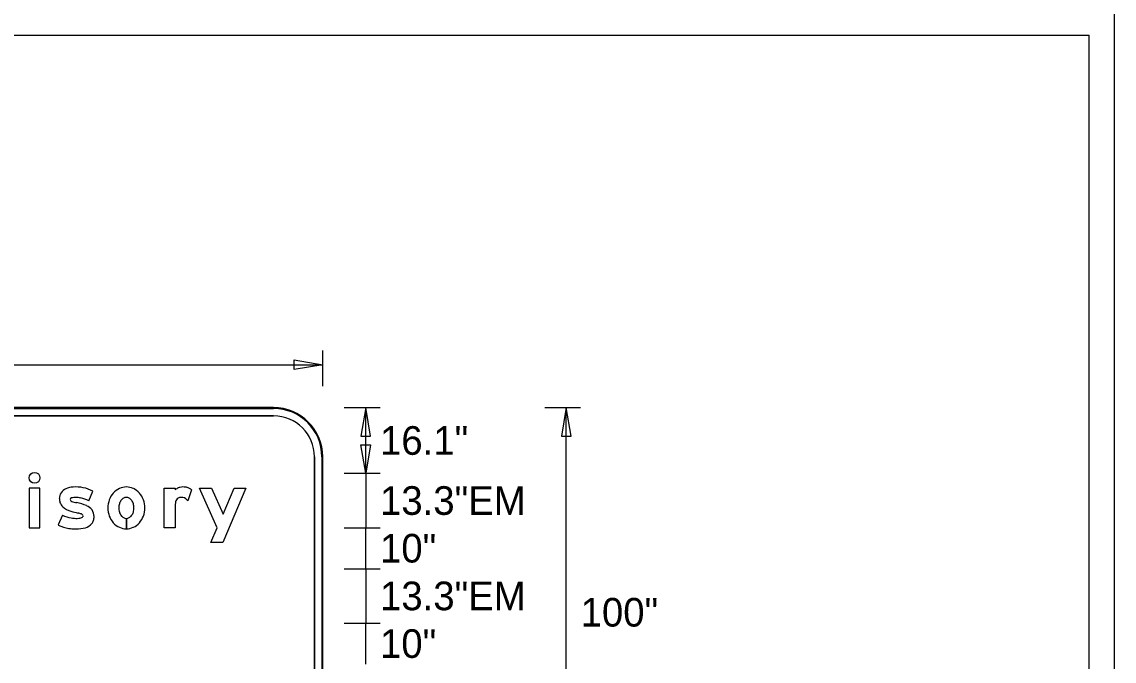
# Model space of a CAD drawing. Extents: x 17890484 to 17890754, y 17897495 to 17897992.
# Drawn here: x 17890542.41 to 17890564.64, y 17897537.69 to 17897550.71 of the extents above; entities that cross this region are included whole.
import ezdxf

# ---------------------------------------------------------------- set-up
doc = ezdxf.new("R2010")
doc.units = 0
for name, color, linetype in [('GSBWFill', 7, 'Continuous'), ('GSColorFill', 7, 'Continuous'), ('GSDims', 7, 'Continuous'), ('GSOutline', 7, 'Continuous'), ('SheetLinesMisc2_dp', 7, 'Continuous')]:
    doc.layers.add(name, color=color, linetype=linetype)

msp = doc.modelspace()

# ---------------------------------------------------------------- linework, layer by layer
at = {"layer": 'GSBWFill'}
for p, q in [((17890547.531, 17897542.854), (17890529.531, 17897542.854)), ((17890529.531, 17897542.687), (17890547.531, 17897542.687)), ((17890548.365, 17897541.854), (17890548.365, 17897533.854)), ((17890548.531, 17897533.854), (17890548.531, 17897541.854)), ((17890543.769, 17897540.955), (17890543.855, 17897541.153)), ((17890545.861, 17897541.181), (17890545.786, 17897540.956)), ((17890543.233, 17897540.663), (17890543.147, 17897540.465)), ((17890544.535, 17897540.386), (17890544.535, 17897540.599)), ((17890544.535, 17897540.599), (17890544.535, 17897540.386)), ((17890543.147, 17897540.465), (17890543.147, 17897540.465))]:
    msp.add_line(p, q, dxfattribs=at)
for points in [[(17890542.555, 17897540.408), (17890542.777, 17897540.408), (17890542.777, 17897541.217), (17890542.555, 17897541.217)], [(17890546.269, 17897541.217), (17890546.503, 17897540.688), (17890546.728, 17897541.217), (17890546.969, 17897541.217), (17890546.498, 17897540.109), (17890546.257, 17897540.109), (17890546.385, 17897540.408), (17890546.027, 17897541.217)]]:
    msp.add_lwpolyline(points, close=True, dxfattribs=at)
msp.add_lwpolyline([(17890545.529, 17897540.856), (17890545.529, 17897540.408), (17890545.307, 17897540.408), (17890545.307, 17897541.217), (17890545.529, 17897541.217), (17890545.529, 17897541.181)], dxfattribs=at)
for radius in [1, 0.833]:
    msp.add_arc((17890547.531, 17897541.854), radius, 0, 90, dxfattribs=at)
msp.add_ellipse((17890542.666, 17897541.425), major_axis=(0, 0.111), ratio=0.999977, dxfattribs=at)
for centre, major_axis, ratio, start_param, end_param in [((17890543.387, 17897541.002), (0, 0.217), 0.999993, 0.398006, 1.570796), ((17890543.482, 17897540.776), (0, 0.462), 0.999993, 0.071378, 0.398007), ((17890543.51, 17897540.642), (0, 0.385), 0.999993, 0, 0.239757), ((17890543.502, 17897540.48), (0, 0.76), 0.999993, 5.800291, 6.352301), ((17890543.51, 17897540.662), (0, 0.364), 0.999993, 6.027142, 6.283185), ((17890544.589, 17897540.832), (0, 0.427), 0.999998, 0.847388, 1.220117), ((17890544.556, 17897540.861), (0, 0.384), 0.999998, 0.438571, 0.847388), ((17890544.535, 17897540.905), (0, 0.334), 0.999998, 0, 0.438571), ((17890544.535, 17897540.912), (0, 0.114), 0.999998, 0, 0.517724), ((17890544.535, 17897540.905), (0, 0.334), 0.999998, 5.844614, 6.283185), ((17890544.535, 17897540.912), (0, 0.114), 0.999998, 5.765461, 6.283185), ((17890544.514, 17897540.861), (0, 0.384), 0.999998, 5.435798, 5.844614), ((17890544.481, 17897540.832), (0, 0.427), 0.999998, 5.063069, 5.435798), ((17890545.752, 17897540.886), (0, 0.37), 0.999991, 0.443663, 0.646229), ((17890545.664, 17897541.07), (0, 0.166), 0.999991, 0.24142, 0.443663), ((17890545.649, 17897540.909), (0, 0.118), 0.999991, 0.067293, 0.293855), ((17890545.693, 17897540.954), (0, 0.285), 0.999991, 6.103268, 6.524606), ((17890545.653, 17897540.85), (0, 0.177), 0.999991, 6.094384, 6.350479), ((17890545.699, 17897540.99), (0, 0.249), 0.999991, 5.846069, 6.103268), ((17890545.674, 17897540.935), (0, 0.31), 0.999991, 5.631644, 5.846069), ((17890543.43, 17897541.002), (0, 0.259), 0.999993, 1.570796, 1.879779), ((17890543.367, 17897540.983), (0, 0.194), 0.999993, 1.879779, 2.42566), ((17890543.523, 17897541.162), (0, 0.432), 0.999993, 2.42566, 2.869403), ((17890543.426, 17897540.983), (0, 0.0332), 0.999993, 0.21891, 1.570796), ((17890543.432, 17897540.983), (0, 0.0388), 0.999993, 1.570796, 2.88808), ((17890543.67, 17897541.735), (0, 0.828), 0.999993, 2.83708, 2.965597), ((17890543.236, 17897539.641), (0, 1.312), 0.999993, 5.901211, 6.060377), ((17890543.485, 17897540.422), (0, 0.604), 0.999993, 5.793797, 6.086746), ((17890543.64, 17897540.635), (0, 0.238), 0.999993, 4.712389, 5.919951), ((17890544.641, 17897540.813), (0, 0.482), 0.999998, 1.220117, 1.570796), ((17890544.641, 17897540.813), (0, 0.482), 0.999998, 1.570796, 1.921476), ((17890544.673, 17897540.813), (0, 0.292), 0.999998, 1.278197, 1.570796), ((17890544.673, 17897540.813), (0, 0.292), 0.999998, 1.570796, 1.863396), ((17890544.605, 17897540.833), (0, 0.222), 0.999998, 0.942, 1.278197), ((17890544.562, 17897540.864), (0, 0.169), 0.999998, 0.517724, 0.942), ((17890544.508, 17897540.864), (0, 0.169), 0.999998, 5.341185, 5.765461), ((17890544.466, 17897540.833), (0, 0.222), 0.999998, 5.004989, 5.341185), ((17890544.398, 17897540.813), (0, 0.292), 0.999998, 4.712389, 5.004989), ((17890544.398, 17897540.813), (0, 0.292), 0.999998, 4.419789, 4.712389), ((17890544.43, 17897540.813), (0, 0.482), 0.999998, 4.712389, 5.063069), ((17890544.43, 17897540.813), (0, 0.482), 0.999998, 4.361709, 4.712389), ((17890545.999, 17897540.855), (0, 0.47), 0.999991, 1.445958, 1.569673), ((17890545.704, 17897540.893), (0, 0.173), 0.999991, 1.188904, 1.450084), ((17890545.647, 17897540.916), (0, 0.111), 0.999991, 0.293855, 1.188904), ((17890545.657, 17897540.874), (0, 0.152), 0.999991, 5.27661, 6.094384), ((17890543.511, 17897541.259), (0, 0.658), 0.999993, 2.70455, 2.991718), ((17890544.148, 17897543.308), (0, 2.667), 0.999993, 2.860128, 2.916667), ((17890543.506, 17897541.104), (0, 0.504), 0.999993, 2.95481, 3.141593), ((17890543.506, 17897541.232), (0, 0.633), 0.999993, 3.141593, 3.238422), ((17890543.276, 17897539.544), (0, 1.197), 0.999993, 5.990951, 6.04928), ((17890543.563, 17897540.752), (0, 0.15), 0.999993, 3.169414, 3.711965), ((17890543.602, 17897540.637), (0, 0.0564), 0.999993, 5.20773, 5.944931), ((17890543.629, 17897540.647), (0, 0.0256), 0.999993, 3.769232, 4.712389), ((17890543.615, 17897540.647), (0, 0.0402), 0.999993, 4.712389, 5.146352), ((17890543.6, 17897540.635), (0, 0.278), 0.999993, 4.42655, 4.712389), ((17890544.589, 17897540.794), (0, 0.427), 0.999998, 1.921476, 2.294205), ((17890544.605, 17897540.792), (0, 0.222), 0.999998, 1.863396, 2.199593), ((17890544.562, 17897540.761), (0, 0.169), 0.999998, 2.199593, 2.623869), ((17890544.535, 17897540.714), (0, 0.114), 0.999998, 2.623869, 3.141593), ((17890544.535, 17897540.714), (0, 0.114), 0.999998, 3.142077, 3.659317), ((17890544.508, 17897540.761), (0, 0.169), 0.999998, 3.659317, 4.083593), ((17890544.466, 17897540.792), (0, 0.222), 0.999998, 4.083593, 4.419789), ((17890544.481, 17897540.794), (0, 0.427), 0.999998, 3.98898, 4.361709), ((17890543.463, 17897541.072), (0, 0.685), 0.999993, 2.661561, 2.999689), ((17890543.444, 17897540.943), (0, 0.554), 0.999993, 2.999689, 3.056979), ((17890543.514, 17897541.747), (0, 1.361), 0.999993, 3.056204, 3.141593), ((17890543.514, 17897541.14), (0, 0.754), 0.999993, 3.141593, 3.39368), ((17890543.63, 17897540.665), (0, 0.265), 0.999993, 3.41426, 4.020407), ((17890543.707, 17897540.603), (0, 0.166), 0.999993, 4.009587, 4.42655), ((17890544.556, 17897540.765), (0, 0.384), 0.999998, 2.294205, 2.703022), ((17890544.535, 17897540.72), (0, 0.334), 0.999998, 2.703022, 3.141593), ((17890544.535, 17897540.72), (0, 0.334), 0.999998, 3.141759, 3.580164), ((17890544.514, 17897540.765), (0, 0.384), 0.999998, 3.580164, 3.98898)]:
    msp.add_ellipse(centre, major_axis=major_axis, ratio=ratio, start_param=start_param, end_param=end_param, dxfattribs=at)
at = {"layer": 'GSColorFill'}
for p, q in [((17890547.531, 17897542.854), (17890529.531, 17897542.854)), ((17890547.531, 17897542.854), (17890529.531, 17897542.854)), ((17890547.531, 17897542.854), (17890529.531, 17897542.854)), ((17890529.531, 17897542.837), (17890547.531, 17897542.837)), ((17890529.531, 17897542.687), (17890547.531, 17897542.687)), ((17890548.365, 17897541.854), (17890548.365, 17897533.854)), ((17890548.515, 17897541.854), (17890548.515, 17897533.854)), ((17890548.531, 17897533.854), (17890548.531, 17897541.854)), ((17890548.531, 17897533.854), (17890548.531, 17897541.854)), ((17890548.531, 17897533.854), (17890548.531, 17897541.854)), ((17890543.769, 17897540.955), (17890543.855, 17897541.153)), ((17890545.861, 17897541.181), (17890545.786, 17897540.956)), ((17890543.233, 17897540.663), (17890543.147, 17897540.465)), ((17890544.535, 17897540.386), (17890544.535, 17897540.599)), ((17890544.535, 17897540.599), (17890544.535, 17897540.386)), ((17890543.147, 17897540.465), (17890543.147, 17897540.465))]:
    msp.add_line(p, q, dxfattribs=at)
for points in [[(17890542.555, 17897540.408), (17890542.777, 17897540.408), (17890542.777, 17897541.217), (17890542.555, 17897541.217)], [(17890546.269, 17897541.217), (17890546.503, 17897540.688), (17890546.728, 17897541.217), (17890546.969, 17897541.217), (17890546.498, 17897540.109), (17890546.257, 17897540.109), (17890546.385, 17897540.408), (17890546.027, 17897541.217)]]:
    msp.add_lwpolyline(points, close=True, dxfattribs=at)
msp.add_lwpolyline([(17890545.529, 17897540.856), (17890545.529, 17897540.408), (17890545.307, 17897540.408), (17890545.307, 17897541.217), (17890545.529, 17897541.217), (17890545.529, 17897541.181)], dxfattribs=at)
for radius in [1, 1, 1, 0.983, 0.833]:
    msp.add_arc((17890547.531, 17897541.854), radius, 0, 90, dxfattribs=at)
msp.add_ellipse((17890542.666, 17897541.425), major_axis=(0, 0.111), ratio=0.999977, dxfattribs=at)
for centre, major_axis, ratio, start_param, end_param in [((17890543.387, 17897541.002), (0, 0.217), 0.999993, 0.398006, 1.570796), ((17890543.482, 17897540.776), (0, 0.462), 0.999993, 0.071378, 0.398007), ((17890543.51, 17897540.642), (0, 0.385), 0.999993, 0, 0.239757), ((17890543.502, 17897540.48), (0, 0.76), 0.999993, 5.800291, 6.352301), ((17890543.51, 17897540.662), (0, 0.364), 0.999993, 6.027142, 6.283185), ((17890544.589, 17897540.832), (0, 0.427), 0.999998, 0.847388, 1.220117), ((17890544.556, 17897540.861), (0, 0.384), 0.999998, 0.438571, 0.847388), ((17890544.535, 17897540.905), (0, 0.334), 0.999998, 0, 0.438571), ((17890544.535, 17897540.912), (0, 0.114), 0.999998, 0, 0.517724), ((17890544.535, 17897540.905), (0, 0.334), 0.999998, 5.844614, 6.283185), ((17890544.535, 17897540.912), (0, 0.114), 0.999998, 5.765461, 6.283185), ((17890544.514, 17897540.861), (0, 0.384), 0.999998, 5.435798, 5.844614), ((17890544.481, 17897540.832), (0, 0.427), 0.999998, 5.063069, 5.435798), ((17890545.752, 17897540.886), (0, 0.37), 0.999991, 0.443663, 0.646229), ((17890545.664, 17897541.07), (0, 0.166), 0.999991, 0.24142, 0.443663), ((17890545.649, 17897540.909), (0, 0.118), 0.999991, 0.067293, 0.293855), ((17890545.693, 17897540.954), (0, 0.285), 0.999991, 6.103268, 6.524606), ((17890545.653, 17897540.85), (0, 0.177), 0.999991, 6.094384, 6.350479), ((17890545.699, 17897540.99), (0, 0.249), 0.999991, 5.846069, 6.103268), ((17890545.674, 17897540.935), (0, 0.31), 0.999991, 5.631644, 5.846069), ((17890543.43, 17897541.002), (0, 0.259), 0.999993, 1.570796, 1.879779), ((17890543.367, 17897540.983), (0, 0.194), 0.999993, 1.879779, 2.42566), ((17890543.523, 17897541.162), (0, 0.432), 0.999993, 2.42566, 2.869403), ((17890543.426, 17897540.983), (0, 0.0332), 0.999993, 0.21891, 1.570796), ((17890543.432, 17897540.983), (0, 0.0388), 0.999993, 1.570796, 2.88808), ((17890543.67, 17897541.735), (0, 0.828), 0.999993, 2.83708, 2.965597), ((17890543.236, 17897539.641), (0, 1.312), 0.999993, 5.901211, 6.060377), ((17890543.485, 17897540.422), (0, 0.604), 0.999993, 5.793797, 6.086746), ((17890543.64, 17897540.635), (0, 0.238), 0.999993, 4.712389, 5.919951), ((17890544.641, 17897540.813), (0, 0.482), 0.999998, 1.220117, 1.570796), ((17890544.641, 17897540.813), (0, 0.482), 0.999998, 1.570796, 1.921476), ((17890544.673, 17897540.813), (0, 0.292), 0.999998, 1.278197, 1.570796), ((17890544.673, 17897540.813), (0, 0.292), 0.999998, 1.570796, 1.863396), ((17890544.605, 17897540.833), (0, 0.222), 0.999998, 0.942, 1.278197), ((17890544.562, 17897540.864), (0, 0.169), 0.999998, 0.517724, 0.942), ((17890544.508, 17897540.864), (0, 0.169), 0.999998, 5.341185, 5.765461), ((17890544.466, 17897540.833), (0, 0.222), 0.999998, 5.004989, 5.341185), ((17890544.398, 17897540.813), (0, 0.292), 0.999998, 4.712389, 5.004989), ((17890544.398, 17897540.813), (0, 0.292), 0.999998, 4.419789, 4.712389), ((17890544.43, 17897540.813), (0, 0.482), 0.999998, 4.712389, 5.063069), ((17890544.43, 17897540.813), (0, 0.482), 0.999998, 4.361709, 4.712389), ((17890545.999, 17897540.855), (0, 0.47), 0.999991, 1.445958, 1.569673), ((17890545.704, 17897540.893), (0, 0.173), 0.999991, 1.188904, 1.450084), ((17890545.647, 17897540.916), (0, 0.111), 0.999991, 0.293855, 1.188904), ((17890545.657, 17897540.874), (0, 0.152), 0.999991, 5.27661, 6.094384), ((17890543.511, 17897541.259), (0, 0.658), 0.999993, 2.70455, 2.991718), ((17890544.148, 17897543.308), (0, 2.667), 0.999993, 2.860128, 2.916667), ((17890543.506, 17897541.104), (0, 0.504), 0.999993, 2.95481, 3.141593), ((17890543.506, 17897541.232), (0, 0.633), 0.999993, 3.141593, 3.238422), ((17890543.276, 17897539.544), (0, 1.197), 0.999993, 5.990951, 6.04928), ((17890543.563, 17897540.752), (0, 0.15), 0.999993, 3.169414, 3.711965), ((17890543.602, 17897540.637), (0, 0.0564), 0.999993, 5.20773, 5.944931), ((17890543.629, 17897540.647), (0, 0.0256), 0.999993, 3.769232, 4.712389), ((17890543.615, 17897540.647), (0, 0.0402), 0.999993, 4.712389, 5.146352), ((17890543.6, 17897540.635), (0, 0.278), 0.999993, 4.42655, 4.712389), ((17890544.589, 17897540.794), (0, 0.427), 0.999998, 1.921476, 2.294205), ((17890544.605, 17897540.792), (0, 0.222), 0.999998, 1.863396, 2.199593), ((17890544.562, 17897540.761), (0, 0.169), 0.999998, 2.199593, 2.623869), ((17890544.535, 17897540.714), (0, 0.114), 0.999998, 2.623869, 3.141593), ((17890544.535, 17897540.714), (0, 0.114), 0.999998, 3.142077, 3.659317), ((17890544.508, 17897540.761), (0, 0.169), 0.999998, 3.659317, 4.083593), ((17890544.466, 17897540.792), (0, 0.222), 0.999998, 4.083593, 4.419789), ((17890544.481, 17897540.794), (0, 0.427), 0.999998, 3.98898, 4.361709), ((17890543.463, 17897541.072), (0, 0.685), 0.999993, 2.661561, 2.999689), ((17890543.444, 17897540.943), (0, 0.554), 0.999993, 2.999689, 3.056979), ((17890543.514, 17897541.747), (0, 1.361), 0.999993, 3.056204, 3.141593), ((17890543.514, 17897541.14), (0, 0.754), 0.999993, 3.141593, 3.39368), ((17890543.63, 17897540.665), (0, 0.265), 0.999993, 3.41426, 4.020407), ((17890543.707, 17897540.603), (0, 0.166), 0.999993, 4.009587, 4.42655), ((17890544.556, 17897540.765), (0, 0.384), 0.999998, 2.294205, 2.703022), ((17890544.535, 17897540.72), (0, 0.334), 0.999998, 2.703022, 3.141593), ((17890544.535, 17897540.72), (0, 0.334), 0.999998, 3.141759, 3.580164), ((17890544.514, 17897540.765), (0, 0.384), 0.999998, 3.580164, 3.98898)]:
    msp.add_ellipse(centre, major_axis=major_axis, ratio=ratio, start_param=start_param, end_param=end_param, dxfattribs=at)
at = {"layer": 'GSDims'}
for p, q in [((17890548.531, 17897543.292), (17890548.531, 17897544.021)), ((17890528.531, 17897543.729), (17890548.531, 17897543.729)), ((17890548.969, 17897542.854), (17890549.698, 17897542.854)), ((17890549.406, 17897541.517), (17890549.406, 17897542.854)), ((17890553.052, 17897542.854), (17890553.781, 17897542.854)), ((17890553.49, 17897534.521), (17890553.49, 17897542.854)), ((17890548.969, 17897541.517), (17890549.698, 17897541.517)), ((17890548.969, 17897541.517), (17890549.698, 17897541.517)), ((17890549.406, 17897541.517), (17890549.406, 17897540.408)), ((17890548.969, 17897540.408), (17890549.698, 17897540.408)), ((17890548.969, 17897540.408), (17890549.698, 17897540.408)), ((17890549.406, 17897539.575), (17890549.406, 17897540.408)), ((17890548.969, 17897539.575), (17890549.698, 17897539.575)), ((17890548.969, 17897539.575), (17890549.698, 17897539.575)), ((17890549.406, 17897539.575), (17890549.406, 17897538.467)), ((17890548.969, 17897538.467), (17890549.698, 17897538.467)), ((17890548.969, 17897538.467), (17890549.698, 17897538.467)), ((17890549.406, 17897537.633), (17890549.406, 17897538.467))]:
    msp.add_line(p, q, dxfattribs=at)
for points in [[(17890548.531, 17897543.729), (17890547.948, 17897543.632), (17890547.948, 17897543.826)], [(17890549.406, 17897542.854), (17890549.309, 17897542.271), (17890549.503, 17897542.271)], [(17890553.49, 17897542.854), (17890553.392, 17897542.271), (17890553.587, 17897542.271)], [(17890549.406, 17897541.517), (17890549.309, 17897542.1), (17890549.503, 17897542.1)]]:
    msp.add_lwpolyline(points, close=True, dxfattribs=at)
at = {"layer": 'GSOutline'}
for p, q in [((17890547.531, 17897542.854), (17890529.531, 17897542.854)), ((17890547.531, 17897542.687), (17890529.531, 17897542.687)), ((17890548.365, 17897533.854), (17890548.365, 17897541.854)), ((17890548.531, 17897533.854), (17890548.531, 17897541.854)), ((17890543.769, 17897540.955), (17890543.855, 17897541.153)), ((17890545.861, 17897541.181), (17890545.786, 17897540.956)), ((17890543.233, 17897540.663), (17890543.147, 17897540.465)), ((17890543.147, 17897540.465), (17890543.147, 17897540.465))]:
    msp.add_line(p, q, dxfattribs=at)
for points in [[(17890542.555, 17897540.408), (17890542.777, 17897540.408), (17890542.777, 17897541.217), (17890542.555, 17897541.217)], [(17890546.269, 17897541.217), (17890546.503, 17897540.688), (17890546.728, 17897541.217), (17890546.969, 17897541.217), (17890546.498, 17897540.109), (17890546.257, 17897540.109), (17890546.385, 17897540.408), (17890546.027, 17897541.217)]]:
    msp.add_lwpolyline(points, close=True, dxfattribs=at)
msp.add_lwpolyline([(17890545.529, 17897540.856), (17890545.529, 17897540.408), (17890545.307, 17897540.408), (17890545.307, 17897541.217), (17890545.529, 17897541.217), (17890545.529, 17897541.181)], dxfattribs=at)
for radius in [1, 0.833]:
    msp.add_arc((17890547.531, 17897541.854), radius, 0, 90, dxfattribs=at)
msp.add_ellipse((17890542.666, 17897541.425), major_axis=(0, 0.111), ratio=0.999977, dxfattribs=at)
for centre, major_axis, ratio, start_param, end_param in [((17890543.387, 17897541.002), (0, 0.217), 0.999993, 0.398006, 1.570796), ((17890543.482, 17897540.776), (0, 0.462), 0.999993, 0.071378, 0.398007), ((17890543.51, 17897540.642), (0, 0.385), 0.999993, 0, 0.239757), ((17890543.502, 17897540.48), (0, 0.76), 0.999993, 5.800291, 6.352301), ((17890543.51, 17897540.662), (0, 0.364), 0.999993, 6.027142, 6.283185), ((17890544.589, 17897540.832), (0, 0.427), 0.999998, 0.847388, 1.220117), ((17890544.556, 17897540.861), (0, 0.384), 0.999998, 0.438571, 0.847388), ((17890544.535, 17897540.905), (0, 0.334), 0.999998, 0, 0.438571), ((17890544.535, 17897540.912), (0, 0.114), 0.999998, 0, 0.517724), ((17890544.535, 17897540.905), (0, 0.334), 0.999998, 5.844614, 6.283185), ((17890544.535, 17897540.912), (0, 0.114), 0.999998, 5.765461, 6.283185), ((17890544.514, 17897540.861), (0, 0.384), 0.999998, 5.435798, 5.844614), ((17890544.481, 17897540.832), (0, 0.427), 0.999998, 5.063069, 5.435798), ((17890545.752, 17897540.886), (0, 0.37), 0.999991, 0.443663, 0.646229), ((17890545.664, 17897541.07), (0, 0.166), 0.999991, 0.24142, 0.443663), ((17890545.649, 17897540.909), (0, 0.118), 0.999991, 0.067293, 0.293855), ((17890545.693, 17897540.954), (0, 0.285), 0.999991, 6.103268, 6.524606), ((17890545.653, 17897540.85), (0, 0.177), 0.999991, 6.094384, 6.350479), ((17890545.699, 17897540.99), (0, 0.249), 0.999991, 5.846069, 6.103268), ((17890545.674, 17897540.935), (0, 0.31), 0.999991, 5.631644, 5.846069), ((17890543.43, 17897541.002), (0, 0.259), 0.999993, 1.570796, 1.879779), ((17890543.367, 17897540.983), (0, 0.194), 0.999993, 1.879779, 2.42566), ((17890543.523, 17897541.162), (0, 0.432), 0.999993, 2.42566, 2.869403), ((17890543.426, 17897540.983), (0, 0.0332), 0.999993, 0.21891, 1.570796), ((17890543.432, 17897540.983), (0, 0.0388), 0.999993, 1.570796, 2.88808), ((17890543.67, 17897541.735), (0, 0.828), 0.999993, 2.83708, 2.965597), ((17890543.236, 17897539.641), (0, 1.312), 0.999993, 5.901211, 6.060377), ((17890543.485, 17897540.422), (0, 0.604), 0.999993, 5.793797, 6.086746), ((17890543.64, 17897540.635), (0, 0.238), 0.999993, 4.712389, 5.919951), ((17890544.641, 17897540.813), (0, 0.482), 0.999998, 1.220117, 1.570796), ((17890544.641, 17897540.813), (0, 0.482), 0.999998, 1.570796, 1.921476), ((17890544.673, 17897540.813), (0, 0.292), 0.999998, 1.278197, 1.570796), ((17890544.673, 17897540.813), (0, 0.292), 0.999998, 1.570796, 1.863396), ((17890544.605, 17897540.833), (0, 0.222), 0.999998, 0.942, 1.278197), ((17890544.562, 17897540.864), (0, 0.169), 0.999998, 0.517724, 0.942), ((17890544.508, 17897540.864), (0, 0.169), 0.999998, 5.341185, 5.765461), ((17890544.466, 17897540.833), (0, 0.222), 0.999998, 5.004989, 5.341185), ((17890544.398, 17897540.813), (0, 0.292), 0.999998, 4.712389, 5.004989), ((17890544.398, 17897540.813), (0, 0.292), 0.999998, 4.419789, 4.712389), ((17890544.43, 17897540.813), (0, 0.482), 0.999998, 4.712389, 5.063069), ((17890544.43, 17897540.813), (0, 0.482), 0.999998, 4.361709, 4.712389), ((17890545.999, 17897540.855), (0, 0.47), 0.999991, 1.445958, 1.569673), ((17890545.704, 17897540.893), (0, 0.173), 0.999991, 1.188904, 1.450084), ((17890545.647, 17897540.916), (0, 0.111), 0.999991, 0.293855, 1.188904), ((17890545.657, 17897540.874), (0, 0.152), 0.999991, 5.27661, 6.094384), ((17890543.511, 17897541.259), (0, 0.658), 0.999993, 2.70455, 2.991718), ((17890544.148, 17897543.308), (0, 2.667), 0.999993, 2.860128, 2.916667), ((17890543.506, 17897541.104), (0, 0.504), 0.999993, 2.95481, 3.141593), ((17890543.506, 17897541.232), (0, 0.633), 0.999993, 3.141593, 3.238422), ((17890543.276, 17897539.544), (0, 1.197), 0.999993, 5.990951, 6.04928), ((17890543.563, 17897540.752), (0, 0.15), 0.999993, 3.169414, 3.711965), ((17890543.602, 17897540.637), (0, 0.0564), 0.999993, 5.20773, 5.944931), ((17890543.629, 17897540.647), (0, 0.0256), 0.999993, 3.769232, 4.712389), ((17890543.615, 17897540.647), (0, 0.0402), 0.999993, 4.712389, 5.146352), ((17890543.6, 17897540.635), (0, 0.278), 0.999993, 4.42655, 4.712389), ((17890544.589, 17897540.794), (0, 0.427), 0.999998, 1.921476, 2.294205), ((17890544.605, 17897540.792), (0, 0.222), 0.999998, 1.863396, 2.199593), ((17890544.562, 17897540.761), (0, 0.169), 0.999998, 2.199593, 2.623869), ((17890544.535, 17897540.714), (0, 0.114), 0.999998, 2.623869, 3.141593), ((17890544.535, 17897540.714), (0, 0.114), 0.999998, 3.141593, 3.659317), ((17890544.508, 17897540.761), (0, 0.169), 0.999998, 3.659317, 4.083593), ((17890544.466, 17897540.792), (0, 0.222), 0.999998, 4.083593, 4.419789), ((17890544.481, 17897540.794), (0, 0.427), 0.999998, 3.98898, 4.361709), ((17890543.463, 17897541.072), (0, 0.685), 0.999993, 2.661561, 2.999689), ((17890543.444, 17897540.943), (0, 0.554), 0.999993, 2.999689, 3.056979), ((17890543.514, 17897541.747), (0, 1.361), 0.999993, 3.056204, 3.141593), ((17890543.514, 17897541.14), (0, 0.754), 0.999993, 3.141593, 3.39368), ((17890543.63, 17897540.665), (0, 0.265), 0.999993, 3.41426, 4.020407), ((17890543.707, 17897540.603), (0, 0.166), 0.999993, 4.009587, 4.42655), ((17890544.556, 17897540.765), (0, 0.384), 0.999998, 2.294205, 2.703022), ((17890544.535, 17897540.72), (0, 0.334), 0.999998, 2.703022, 3.141593), ((17890544.535, 17897540.72), (0, 0.334), 0.999998, 3.141593, 3.580164), ((17890544.514, 17897540.765), (0, 0.384), 0.999998, 3.580164, 3.98898)]:
    msp.add_ellipse(centre, major_axis=major_axis, ratio=ratio, start_param=start_param, end_param=end_param, dxfattribs=at)
at = {"layer": 'SheetLinesMisc2_dp'}
for p, q in [((17890564.641, 17897597.808), (17890564.641, 17897504.15)), ((17890512.958, 17897550.442), (17890564.13, 17897550.442)), ((17890564.129, 17897525.552), (17890564.129, 17897550.443))]:
    msp.add_line(p, q, dxfattribs=at)

# ---------------------------------------------------------------- texts
at = {"layer": 'GSDims'}
for s, p in [('16.1"', (17890549.698, 17897541.894)), ('13.3"EM', (17890549.698, 17897540.671)), ('10"', (17890549.698, 17897539.7)), ('13.3"EM', (17890549.698, 17897538.729)), ('100"', (17890553.781, 17897538.396)), ('10"', (17890549.698, 17897537.758))]:
    msp.add_text(s, height=0.5833, dxfattribs=at).set_placement(p)

doc.saveas('drawing.dxf')
